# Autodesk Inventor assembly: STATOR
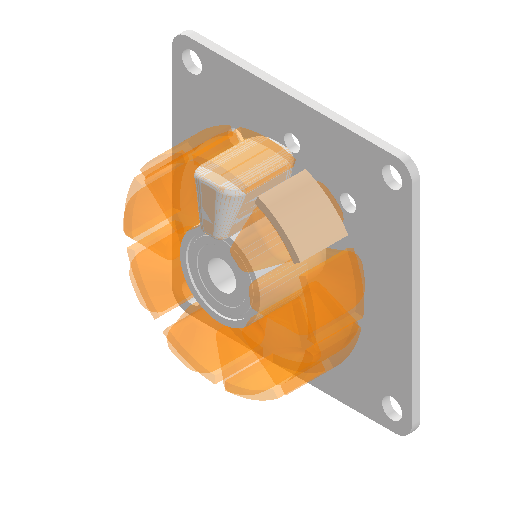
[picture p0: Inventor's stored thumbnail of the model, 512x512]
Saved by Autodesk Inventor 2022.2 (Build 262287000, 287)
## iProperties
Created: 2025-01
Part Number: STATOR
Document SubType Name: Assembly
Designer: 18907419
Author: 18907419
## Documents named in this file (5)
- C:\Users\18907419\Desktop\mini\Creo\STATOR.iam
- C:\Users\18907419\Desktop\mini\Creo\BASE.ipt
- C:\Users\18907419\Desktop\mini\Creo\STATOR.ipt
- C:\Users\18907419\Desktop\mini\Creo\CHARBON.ipt
- C:\Users\18907419\Desktop\mini\Creo\AXE.ipt
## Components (4 placed, 4 different names)
1. BASE
2. STATOR
3. CHARBON
4. AXE
